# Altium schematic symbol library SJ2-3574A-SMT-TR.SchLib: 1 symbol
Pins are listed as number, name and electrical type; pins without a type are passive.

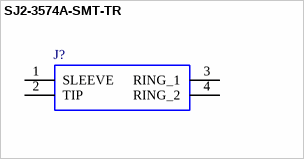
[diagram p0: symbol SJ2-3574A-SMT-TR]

## SJ2-3574A-SMT-TR
designator J?
Phone Connectors 3.5mm Audio Jack SMT 4 conductor 0 switch; Manufacturer_Name: CUI Inc.; Geometry.Height: 5mm
footprint SJ23574ASMTTR
pins: 1 SLEEVE, 2 TIP, 3 RING_1, 4 RING_2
